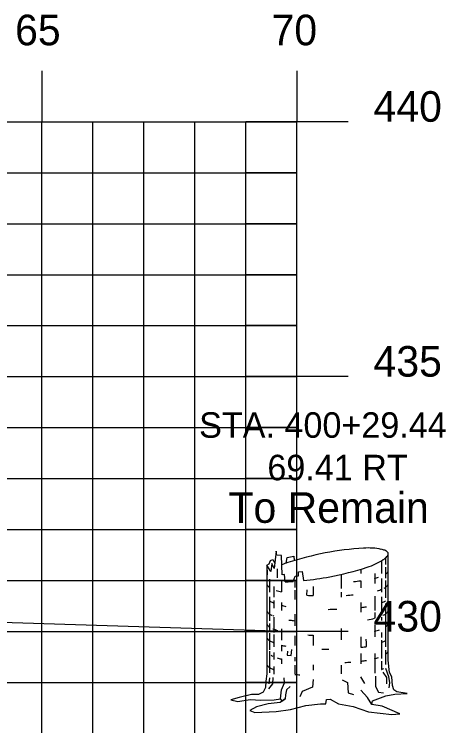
# Model space of a CAD drawing. Extents: x -161 to 764, y 111 to 210.
# Drawn here: x -23.23 to -14.78, y 186.58 to 200.54 of the extents above; entities that cross this region are included whole.
import ezdxf

# ---------------------------------------------------------------- set-up
doc = ezdxf.new("R2010")
doc.units = 0
for name, color, linetype in [('D_Text_Monospaced', 7, 'Continuous'), ('D_Text_Standard', 7, 'Continuous'), ('H_V ANNOTATION', 7, 'Continuous'), ('MAJOR', 7, 'Continuous'), ('MINOR', 7, 'Continuous'), ('S_Roadway_Centerline', 7, 'Continuous'), ('S_Trees_Decid_Pay', 7, 'Continuous')]:
    doc.layers.add(name, color=color, linetype=linetype)

msp = doc.modelspace()

# ---------------------------------------------------------------- linework, layer by layer
at = {"layer": 'MAJOR'}
for p, q in [((-22.693, 199.435), (-22.693, 198.433)), ((-17.693, 199.435), (-17.693, 198.433)), ((-157.693, 198.433), (-17.693, 198.433)), ((-157.693, 198.433), (-17.693, 198.433)), ((-22.693, 178.433), (-22.693, 198.433)), ((-16.691, 198.433), (-18.695, 198.433)), ((-17.693, 178.433), (-17.693, 198.433)), ((-17.693, 178.433), (-17.693, 198.433)), ((-157.693, 193.433), (-17.693, 193.433)), ((-16.691, 193.433), (-18.695, 193.433)), ((-157.693, 188.433), (-17.693, 188.433)), ((-16.691, 188.433), (-18.695, 188.433))]:
    msp.add_line(p, q, dxfattribs=at)
at = {"layer": 'MINOR'}
for p, q in [((-21.693, 178.433), (-21.693, 198.433)), ((-20.693, 178.433), (-20.693, 198.433)), ((-19.693, 178.433), (-19.693, 198.433)), ((-18.693, 178.433), (-18.693, 198.433)), ((-157.693, 197.433), (-17.693, 197.433)), ((-17.693, 197.433), (-18.695, 197.433)), ((-157.693, 196.433), (-17.693, 196.433)), ((-17.693, 196.433), (-18.695, 196.433)), ((-157.693, 195.433), (-17.693, 195.433)), ((-17.693, 195.433), (-18.695, 195.433)), ((-157.693, 194.433), (-17.693, 194.433)), ((-17.693, 194.433), (-18.695, 194.433)), ((-157.693, 192.433), (-17.693, 192.433)), ((-17.693, 192.433), (-18.695, 192.433)), ((-157.693, 191.433), (-17.693, 191.433)), ((-17.693, 191.433), (-18.695, 191.433)), ((-157.693, 190.433), (-17.693, 190.433)), ((-17.693, 190.433), (-18.695, 190.433)), ((-157.693, 189.433), (-17.693, 189.433)), ((-17.693, 189.433), (-18.695, 189.433)), ((-157.693, 187.433), (-17.693, 187.433)), ((-17.693, 187.433), (-18.695, 187.433))]:
    msp.add_line(p, q, dxfattribs=at)
at = {"layer": 'S_Roadway_Centerline'}
msp.add_lwpolyline([(-157.693, 186.896), (-152.22, 186.735), (-150.498, 186.807), (-148.901, 186.975), (-141.893, 187.734), (-139.882, 188.09), (-132.124, 189.256), (-128.171, 189.315), (-121.467, 188.992), (-115.974, 188.872), (-110.769, 188.6), (-96.239, 188.433), (-93.99, 188.538), (-87.1, 188.918), (-86.065, 188.968), (-75.289, 189.172), (-68.973, 189.373), (-42.532, 188.98), (-34.493, 188.828), (-32.191, 188.81), (-29.47, 188.805), (-17.693, 188.431)], dxfattribs=at)
at = {"layer": 'S_Trees_Decid_Pay'}
for p, q in [((-15.959, 189.867), (-15.959, 189.746)), ((-16.039, 189.822), (-16.039, 189.569)), ((-15.959, 189.694), (-15.959, 189.48)), ((-18.084, 189.663), (-18.084, 189.489)), ((-16.827, 189.554), (-16.827, 189.274)), ((-16.444, 189.655), (-16.444, 189.569)), ((-16.171, 189.569), (-16.171, 189.377)), ((-18.233, 189.463), (-18.233, 189.208)), ((-17.999, 189.414), (-17.999, 189.21)), ((-17.738, 189.416), (-17.738, 189.297)), ((-16.444, 189.428), (-16.444, 189.288)), ((-16.039, 189.472), (-16.039, 189.208)), ((-15.959, 189.435), (-15.959, 189.097)), ((-18.147, 189.317), (-18.147, 189.105)), ((-17.373, 189.317), (-17.373, 189.138)), ((-17.738, 189.245), (-17.738, 189.06)), ((-17.5, 189.145), (-17.494, 189.252)), ((-16.827, 189.208), (-16.827, 189.105)), ((-18.233, 189.111), (-18.233, 188.642)), ((-18.147, 189.04), (-18.147, 188.891)), ((-17.999, 189.002), (-17.999, 188.848)), ((-16.444, 189.002), (-16.444, 188.811)), ((-16.171, 189.126), (-16.171, 188.848)), ((-16.039, 189.111), (-16.039, 188.803)), ((-15.959, 188.98), (-15.959, 188.619)), ((-18.147, 188.714), (-18.147, 188.414)), ((-17.738, 188.774), (-17.738, 188.546)), ((-16.171, 188.803), (-16.171, 188.694)), ((-16.039, 188.714), (-16.039, 188.648)), ((-18.233, 188.591), (-18.233, 188.457)), ((-15.959, 188.582), (-15.959, 188.134)), ((-17.999, 188.485), (-17.999, 188.266)), ((-16.827, 188.494), (-16.827, 188.273)), ((-16.171, 188.559), (-16.171, 188.331)), ((-18.233, 188.399), (-18.233, 188.074)), ((-18.147, 188.376), (-18.147, 188.134)), ((-17.738, 188.348), (-17.738, 188.162)), ((-17.373, 188.359), (-17.373, 188.162)), ((-16.444, 188.331), (-16.444, 188.123)), ((-16.039, 188.414), (-16.039, 188.317)), ((-17.999, 188.166), (-17.999, 188.045)), ((-16.039, 188.266), (-16.039, 187.905)), ((-18.233, 188.045), (-18.233, 187.625)), ((-18.147, 188.023), (-18.147, 187.882)), ((-15.959, 188.068), (-15.959, 187.786)), ((-17.999, 187.894), (-17.999, 187.796)), ((-17.738, 187.928), (-17.738, 187.851)), ((-16.444, 188.002), (-16.444, 187.802)), ((-16.171, 188.002), (-16.171, 187.619)), ((-18.147, 187.75), (-18.147, 187.594)), ((-17.738, 187.773), (-17.738, 187.6)), ((-17.373, 187.779), (-17.373, 187.676)), ((-16.827, 187.773), (-16.827, 187.6)), ((-16.039, 187.853), (-16.039, 187.687)), ((-18.23, 187.522), (-18.244, 187.405)), ((-16.448, 187.545), (-16.368, 187.413))]:
    msp.add_line(p, q, dxfattribs=at)
for points in [[(-17.927, 189.41), (-17.935, 189.554), (-17.98, 189.546), (-17.995, 189.921), (-18.089, 189.929), (-18.104, 190.009), (-18.141, 189.672), (-18.187, 189.766), (-18.207, 189.612), (-18.284, 189.737), (-18.278, 189.548)], [(-18.284, 189.737), (-18.284, 187.6), (-18.304, 187.458), (-18.31, 187.332), (-18.353, 187.246), (-18.446, 187.197), (-18.582, 187.197), (-18.825, 187.141), (-18.992, 187.092), (-18.849, 187.061), (-18.612, 187.098), (-18.402, 187.086), (-18.141, 187.092), (-18.017, 187.11), (-17.987, 187.067), (-17.925, 187.11), (-18.024, 187.042), (-18.259, 187.017), (-18.489, 186.956), (-18.619, 186.886), (-18.52, 186.842), (-18.098, 186.861), (-17.82, 186.905), (-17.521, 186.981), (-17.235, 187.017), (-17.13, 187.017), (-17.112, 187.098), (-17.043, 187.104), (-16.877, 187.017), (-16.591, 186.962), (-16.292, 186.855), (-15.833, 186.806), (-15.679, 186.818), (-16.021, 186.968), (-16.224, 186.999), (-16.212, 187.073), (-15.952, 187.172), (-15.777, 187.203), (-15.536, 187.215), (-15.734, 187.252), (-15.796, 187.289), (-15.82, 187.376), (-15.833, 187.545), (-15.878, 187.631), (-15.906, 187.872), (-15.906, 189.958)], [(-18.284, 189.737), (-18.238, 189.76), (-18.215, 189.826), (-18.164, 189.849), (-18.13, 189.774)], [(-17.905, 189.776), (-17.884, 189.884), (-17.752, 189.914), (-17.745, 189.827)], [(-17.766, 189.414), (-17.729, 189.517), (-17.664, 189.523), (-17.664, 189.605), (-17.589, 189.612), (-17.564, 189.432)], [(-16.33, 188.137), (-16.332, 188.214), (-16.339, 188.28)], [(-17.876, 188.045), (-17.884, 187.971), (-17.81, 187.965), (-17.795, 188.082)], [(-16.014, 187.633), (-15.942, 187.53), (-15.942, 187.405)], [(-15.957, 187.714), (-15.897, 187.553), (-15.883, 187.428), (-15.891, 187.33)], [(-18.164, 187.53), (-18.17, 187.405), (-18.252, 187.31)], [(-18.017, 187.11), (-17.999, 187.289), (-17.937, 187.426), (-17.944, 187.526)], [(-17.375, 187.493), (-17.392, 187.339), (-17.589, 187.258), (-17.635, 187.155)], [(-16.809, 187.485), (-16.706, 187.433), (-16.692, 187.227), (-16.589, 187.199)], [(-16.154, 187.559), (-16.154, 187.353), (-16.097, 187.244), (-16, 187.227)], [(-17.826, 187.357), (-17.9, 187.289), (-17.919, 187.191), (-17.925, 187.11)], [(-16.224, 186.999), (-16.311, 187.141), (-16.442, 187.283)]]:
    msp.add_lwpolyline(points, dxfattribs=at)
for centre, radius, start, end in [((-15.994, 183.956), 6.126, 100.7779, 107.8613), ((-15.994, 183.956), 6.126, 93.6944, 100.7779), ((-16.305, 188.773), 1.299, 78.2779, 93.6944), ((-16.138, 189.575), 0.48, 69.9843, 78.2779), ((-16.03, 189.872), 0.164, 55.7779, 69.9843), ((-15.998, 189.919), 0.107, 45.9547, 55.7779), ((-15.968, 189.949), 0.0645, 33.2779, 45.9547), ((-15.96, 189.955), 0.0544, 22.46, 33.2779), ((-15.953, 189.958), 0.0467, 10.7779, 22.46), ((-16.716, 190.931), 1.299, 287.8613, 303.2779), ((-16.266, 190.246), 0.48, 303.2779, 311.5714), ((-16.056, 190.01), 0.164, 311.5714, 325.7779), ((-16.009, 189.978), 0.107, 325.7779, 335.6011), ((-15.971, 189.96), 0.0645, 335.6011, 348.2779), ((-15.953, 189.958), 0.0467, 359.0957, 10.7779), ((-15.961, 189.958), 0.0544, 348.2779, 359.0957), ((-17.474, 188.55), 1.299, 107.8613, 113.3069), ((-18.196, 195.525), 6.126, 280.7779, 287.8613), ((-16.046, 189.701), 0.166, 301.67, 315), ((-16.005, 189.66), 0.109, 315, 324.8263), ((-15.97, 189.635), 0.0657, 324.8263, 337.5), ((-15.96, 189.631), 0.0554, 337.5, 348.3185), ((-17.885, 190.709), 1.299, 268.1289, 273.6944), ((-18.196, 195.525), 6.126, 273.6944, 274.0246), ((-18.196, 195.525), 6.126, 275.9147, 280.7779), ((-17.094, 195.308), 5.916, 274.9514, 276.3087), ((-16.518, 190.72), 1.292, 285.5651, 289.0916), ((-18.236, 189.369), 0.0476, 180, 191.6815), ((-18.228, 189.371), 0.0554, 191.6815, 202.5), ((-18.219, 189.374), 0.0657, 202.5, 215.1737), ((-18.183, 189.399), 0.109, 215.1737, 225), ((-18.143, 189.44), 0.166, 225, 239.1924), ((-16.21, 189.713), 0.484, 297.4162, 300.8076), ((-16.047, 189.44), 0.166, 300.8076, 315), ((-16.006, 189.399), 0.109, 315, 324.8263), ((-15.971, 189.374), 0.0657, 324.8263, 337.5), ((-15.961, 189.371), 0.0554, 337.5, 348.3185), ((-17.671, 190.459), 1.292, 250.6119, 255.2856), ((-17.095, 195.047), 5.916, 266.0776, 267.3043), ((-17.095, 195.047), 5.916, 273.5382, 274.8924), ((-16.519, 190.459), 1.292, 288.0829, 292.5), ((-18.143, 189.176), 0.166, 237.0378, 239.1924), ((-17.98, 189.449), 0.484, 239.1924, 247.5), ((-17.671, 190.196), 1.292, 247.5, 248.3537), ((-16.519, 190.196), 1.292, 291.8071, 292.5), ((-16.21, 189.449), 0.484, 292.5, 300.8076), ((-16.047, 189.176), 0.166, 300.8076, 301.6001), ((-17.671, 190.196), 1.292, 255.2856, 259.2632), ((-17.095, 194.784), 5.916, 270.1162, 271.7708), ((-17.095, 194.784), 5.916, 276.3183, 277.1546), ((-16.519, 190.196), 1.292, 277.1546, 278.3662), ((-18.236, 188.848), 0.0476, 180, 191.6815), ((-18.228, 188.85), 0.0554, 191.6815, 202.5), ((-18.219, 188.854), 0.0657, 202.5, 215.1737), ((-18.183, 188.879), 0.109, 215.1737, 225), ((-18.143, 188.919), 0.166, 225, 239.1924), ((-17.98, 189.192), 0.484, 239.1924, 245.7724), ((-17.671, 189.938), 1.292, 247.5, 248.4842), ((-16.21, 189.192), 0.484, 294.6372, 300.8076), ((-16.047, 188.919), 0.166, 300.8076, 315), ((-16.006, 188.879), 0.109, 315, 324.8263), ((-15.971, 188.854), 0.0657, 324.8263, 337.5), ((-15.961, 188.85), 0.0554, 337.5, 348.3185), ((-18.236, 188.591), 0.0476, 180, 191.6815), ((-18.228, 188.592), 0.0554, 191.6815, 202.5), ((-17.671, 189.938), 1.292, 261.8726, 262.8454), ((-17.095, 194.526), 5.916, 262.8454, 263.7595), ((-16.519, 189.938), 1.292, 279.2565, 285.6105), ((-15.961, 188.592), 0.0554, 337.5, 348.3185), ((-18.219, 188.596), 0.0657, 202.5, 215.1737), ((-18.183, 188.621), 0.109, 215.1737, 225), ((-18.143, 188.662), 0.166, 225, 239.1924), ((-17.671, 189.681), 1.292, 247.5, 251.799), ((-16.519, 189.681), 1.292, 285.6105, 290.1001), ((-16.047, 188.662), 0.166, 302.0694, 315), ((-16.006, 188.621), 0.109, 315, 324.8263), ((-15.971, 188.596), 0.0657, 324.8263, 337.5), ((-18.236, 188.325), 0.0476, 180, 191.6815), ((-18.228, 188.327), 0.0554, 191.6815, 202.5), ((-18.219, 188.331), 0.0657, 202.5, 215.1737), ((-18.183, 188.356), 0.109, 215.1737, 225), ((-17.095, 194.269), 5.916, 266.2721, 267.3043), ((-15.961, 188.327), 0.0554, 337.5, 348.3185), ((-18.143, 188.396), 0.166, 225, 239.1924), ((-17.98, 188.669), 0.484, 239.1924, 247.5), ((-17.671, 189.415), 1.292, 247.5, 248.3537), ((-17.671, 189.415), 1.292, 255.2856, 259.2463), ((-16.21, 188.669), 0.484, 292.5, 300.8076), ((-16.047, 188.396), 0.166, 300.8076, 302.0694), ((-17.095, 194.003), 5.916, 268.9206, 270), ((-17.095, 194.003), 5.916, 270, 270.2757), ((-17.095, 194.003), 5.916, 276.3183, 277.1546), ((-16.519, 189.415), 1.292, 277.1546, 278.3795), ((-16.006, 188.084), 0.109, 315, 324.8263), ((-15.971, 188.059), 0.0657, 324.8263, 337.5), ((-15.961, 188.055), 0.0554, 337.5, 348.3185), ((-17.98, 188.397), 0.484, 242.734, 247.5), ((-17.671, 189.144), 1.292, 251.3664, 255.2856), ((-16.519, 189.144), 1.292, 285.6105, 289.1534), ((-16.047, 188.124), 0.166, 302.0694, 315), ((-18.236, 187.796), 0.0476, 180, 191.6815), ((-18.228, 187.797), 0.0554, 191.6815, 202.5), ((-18.219, 187.801), 0.0657, 202.5, 215.1737), ((-18.183, 187.826), 0.109, 215.1737, 225), ((-18.143, 187.867), 0.166, 225, 239.1924), ((-17.095, 193.732), 5.916, 273.2637, 274.461), ((-17.095, 193.732), 5.916, 276.3183, 277.1546), ((-16.519, 189.144), 1.292, 277.1546, 278.3662), ((-17.98, 188.14), 0.484, 239.1924, 247.5), ((-17.671, 188.886), 1.292, 247.5, 248.3537), ((-16.51, 188.89), 1.292, 291.3696, 292.0604), ((-16.21, 188.14), 0.484, 292.5, 296.5499), ((-17.095, 193.474), 5.916, 263.7831, 264.7655)]:
    msp.add_arc(centre, radius, start, end, dxfattribs=at)

# ---------------------------------------------------------------- texts
at = {"layer": 'D_Text_Monospaced'}
for s, height, p in [('STA. 400+29.44', 0.49998, (-19.61, 192.234)), ('69.41 RT', 0.5, (-18.273, 191.4))]:
    msp.add_text(s, height=height, dxfattribs=at).set_placement(p)
at = {"layer": 'D_Text_Standard'}
msp.add_text('To Remain', height=0.6, dxfattribs=at).set_placement((-19.035, 190.565))
at = {"layer": 'H_V ANNOTATION'}
for s, p in [('65', (-23.215, 199.933)), ('70', (-18.191, 199.933)), ('440', (-16.193, 198.433)), ('435', (-16.193, 193.433)), ('430', (-16.193, 188.433))]:
    msp.add_text(s, height=0.6, rotation=360, dxfattribs=at).set_placement(p)

doc.saveas('drawing.dxf')
